Omron CX-Programmer project NuevoProyecto (CX-Programmer 9.50)

# PLC NewPLC1: CP1L-E EM

## Program P7_3 (cyclic task 0)
Local symbols
Ab 100.01 BOOL
As 100.00 BOOL
B 100.02 BOOL
C 100.03 BOOL
Etapa_0 10.00 BOOL
Etapa_1 10.01 BOOL
Etapa_10 10.07 BOOL
Etapa_11 10.08 BOOL
Etapa_12 10.09 BOOL
Etapa_13 10.10 BOOL
Etapa_2 10.02 BOOL
Etapa_3 10.03 BOOL
Etapa_4 10.04 BOOL
Etapa_5 10.05 BOOL
Etapa_E1 10.06 BOOL
Etapa_S1 10.11 BOOL
a_0 0.01 BOOL
a_1 0.02 BOOL
a_2 0.03 BOOL
b_0 0.04 BOOL
b_1 0.05 BOOL
c_0 0.06 BOOL
c_1 0.07 BOOL
m 0.00 BOOL

### Section Sección1_Programa_principal
; Programa principal (Etapas 0 ... 7)

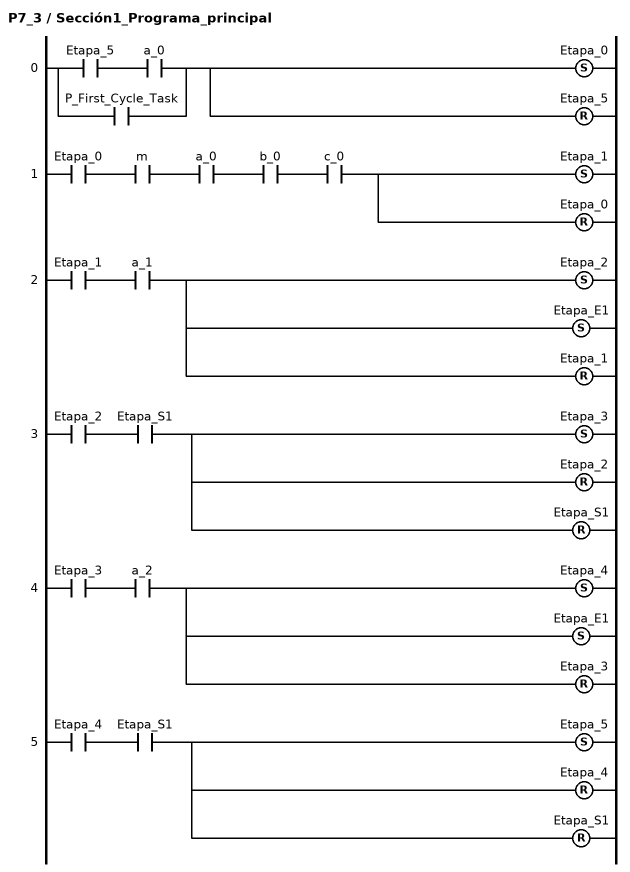
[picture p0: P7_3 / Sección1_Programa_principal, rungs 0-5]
; rung 0
LD Etapa_5
AND a_0
OR P_First_Cycle_Task
SET Etapa_0
RSET Etapa_5
; rung 1
LD Etapa_0
AND m
AND a_0
AND b_0
AND c_0
SET Etapa_1
RSET Etapa_0
; rung 2
LD Etapa_1
AND a_1
SET Etapa_2
SET Etapa_E1
RSET Etapa_1
; rung 3
LD Etapa_2
AND Etapa_S1
SET Etapa_3
RSET Etapa_2
RSET Etapa_S1
; rung 4
LD Etapa_3
AND a_2
SET Etapa_4
SET Etapa_E1
RSET Etapa_3
; rung 5
LD Etapa_4
AND Etapa_S1
SET Etapa_5
RSET Etapa_4
RSET Etapa_S1

### Section Sección2_Macroetapa

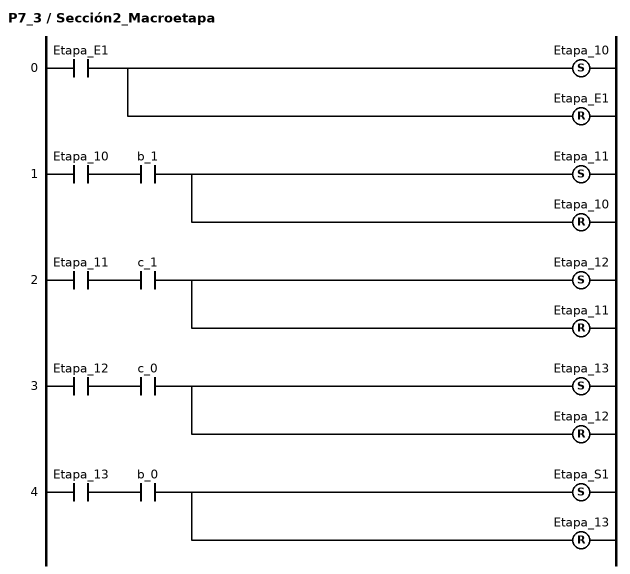
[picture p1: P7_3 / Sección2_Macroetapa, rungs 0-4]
; rung 0
LD Etapa_E1
SET Etapa_10
RSET Etapa_E1
; rung 1
LD Etapa_10
AND b_1
SET Etapa_11
RSET Etapa_10
; rung 2
LD Etapa_11
AND c_1
SET Etapa_12
RSET Etapa_11
; rung 3
LD Etapa_12
AND c_0
SET Etapa_13
RSET Etapa_12
; rung 4
LD Etapa_13
AND b_0
SET Etapa_S1
RSET Etapa_13

### Section Sección3_Salidas

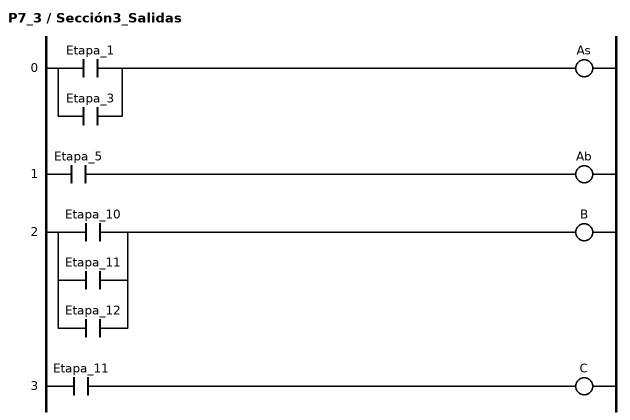
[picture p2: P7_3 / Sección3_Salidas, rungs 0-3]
; rung 0
LD Etapa_1
OR Etapa_3
OUT As
; rung 1
LD Etapa_5
OUT Ab
; rung 2
LD Etapa_10
OR Etapa_11
OR Etapa_12
OUT B
; rung 3
LD Etapa_11
OUT C

### Section Sección4_END
; rung 0: Fin de programa
END(001)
